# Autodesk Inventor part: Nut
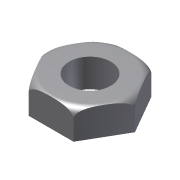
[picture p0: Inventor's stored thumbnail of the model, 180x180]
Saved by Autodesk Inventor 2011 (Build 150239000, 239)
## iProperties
Created: 2009-04
Part Number: Nut
Document SubType Name: Modeling
Designer: Sham
Density: 1 g/cm^3
Author: Sham
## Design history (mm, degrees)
sketch "Sketch1"
  geometry: L1 (19.919, 34.5)-(39.837, 0); L2 (39.837, 0)-(19.919, -34.5); L3 (19.919, -34.5)-(-19.919, -34.5); L4 (-19.919, -34.5)-(-39.837, 0); L5 (-39.837, 0)-(-19.919, 34.5); L6 (-19.919, 34.5)-(19.919, 34.5); C1 r 18.5 at (0, 0); 1 further point
  constraints: 12 end point, 1 centre point, 1 coincident, 13 other
  dimensions: "d0" = 69 distance between parallel lines of L3 L6; "d1" = 37 diameter of C1
extrude "Extrusion1" new body sketch "Sketch1" distance "d2" = 25; taper "d3" = 0 deg
sketch "Sketch2"
  geometry: L1 (0, -5.4)-(0, 32.4) reference; L2 (-19.919, 25)-(-39.837, 25) reference; L3 (-19.919, 25)-(-39.837, 25) reference; L4 (-39.837, 0)-(-39.837, 25) reference; L5 (-19.919, 0)-(-39.837, 0) reference; L6 (-19.919, 0)-(-19.919, 25) reference; A1 r 7.5 centre (-32.337, 17.5) between (-32.337, 25) and (-39.837, 17.5); 1 further point
  constraints: 2 midpoint, 2 point on circle, 2 point on line, 2 tangent, 1 centre point
  dimensions: "d6" = 7.5 radius of A1
revolve "Revolution1" sketch "Sketch2" stored, may be unused: angle "d5" = 90 deg
body "Solid1"
node "Projected Loop1"
other parameters: "d4" = 90 deg
